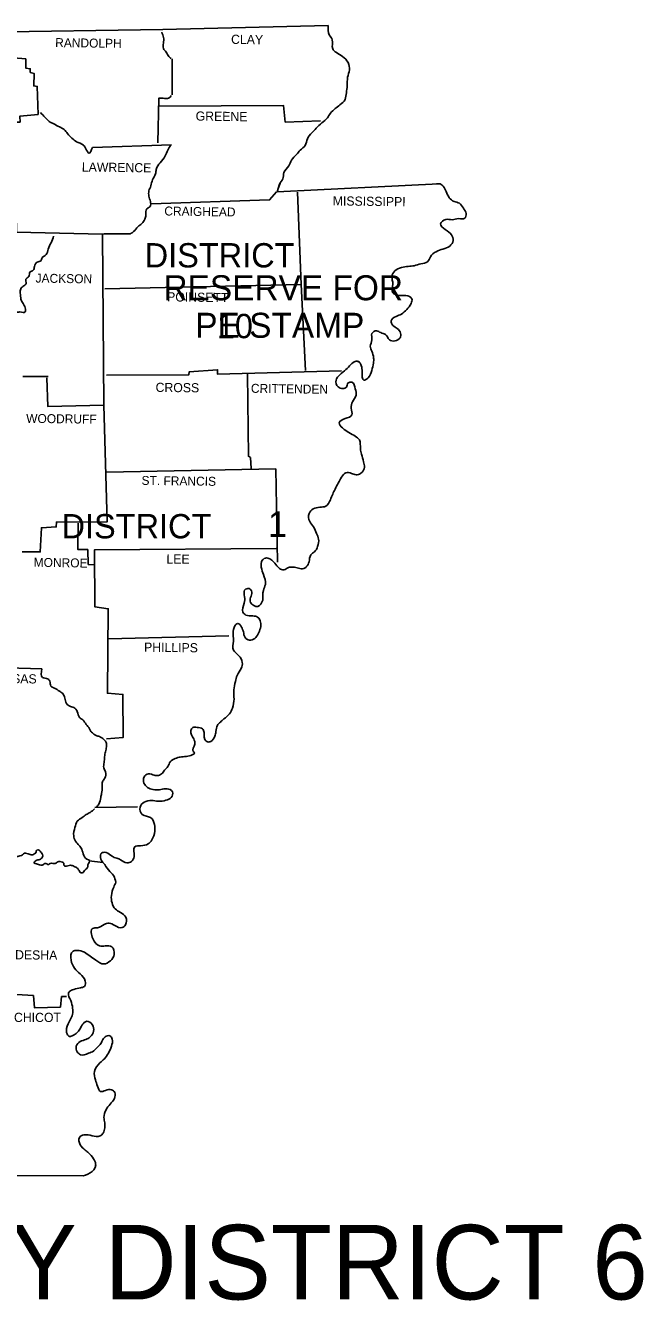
# Model space of a CAD drawing. Extents: x 1096785 to 1382432, y 216169 to 341661.
# Drawn here: x 1237243 to 1243040, y 280666 to 292630 of the extents above; entities that cross this region are included whole.
import ezdxf

# ---------------------------------------------------------------- set-up
doc = ezdxf.new("R2010")
doc.units = 0
for name, color, linetype in [('1', 7, 'Continuous'), ('21', 7, 'Continuous'), ('3', 7, 'Continuous'), ('36', 7, 'Continuous')]:
    doc.layers.add(name, color=color, linetype=linetype)

msp = doc.modelspace()

# ---------------------------------------------------------------- linework, layer by layer
at = {"layer": '1'}
for p, q in [((1239603, 291068), (1239627, 291142)), ((1239609, 291092), (1239633, 291150)), ((1237219, 289336), (1237457, 289336)), ((1237895, 285292), (1238295, 285298)), ((1237967, 284776), (1237841, 284792))]:
    msp.add_line(p, q, dxfattribs=at)
for points in [[(1229111, 292538), (1232345, 292536), (1235183, 292542), (1238531, 292594), (1240083, 292630)], [(1237443, 289324), (1237453, 289054), (1237979, 289068), (1237965, 290672), (1237159, 290690), (1237141, 291722), (1237193, 291724), (1237191, 291780), (1237361, 291796), (1237353, 292058), (1237321, 292064), (1237323, 292180), (1237287, 292190), (1237287, 292224), (1237245, 292230), (1237245, 292316), (1237131, 292328), (1237125, 292424), (1237103, 292438), (1237099, 292470), (1237053, 292480), (1237055, 292504), (1237015, 292510), (1237021, 292558)], [(1238619, 292318), (1238619, 291980)], [(1238483, 291530), (1238493, 291948), (1238493, 291874), (1239663, 291880), (1239679, 291724), (1240009, 291736)], [(1237871, 291486), (1238613, 291512)], [(1239603, 291068), (1241121, 291146)], [(1238423, 290958), (1239533, 290994), (1239599, 291070)], [(1239795, 291066), (1239829, 290200), (1239869, 289394)], [(1238227, 290676), (1237983, 290676), (1237965, 290672)], [(1239829, 290200), (1237987, 290158)], [(1238003, 289348), (1238775, 289352), (1238777, 289380), (1239045, 289400), (1239045, 289358), (1240209, 289390)], [(1239325, 289358), (1239335, 288588), (1239353, 288576), (1239359, 288472)], [(1237979, 289068), (1238009, 287972), (1237533, 287970), (1237531, 287926), (1237393, 287918), (1237381, 287690), (1237213, 287690)], [(1238003, 288438), (1239591, 288470)], [(1239591, 288470), (1239607, 287594)], [(1237737, 287960), (1237735, 287712), (1237827, 287712), (1237831, 287574), (1237889, 287568)], [(1238003, 285938), (1238159, 285948), (1238157, 286354), (1238011, 286364), (1238019, 287158), (1237893, 287176), (1237889, 287710), (1239595, 287722)], [(1238023, 286876), (1239151, 286904)], [(1237397, 286594), (1236641, 286614), (1236637, 286368), (1235107, 286362)], [(1237785, 281836), (1230455, 281848), (1230451, 283466)], [(1237049, 283544), (1237317, 283528), (1237329, 283412), (1237571, 283420), (1237581, 283518), (1237627, 283518)]]:
    msp.add_lwpolyline(points, dxfattribs=at)
for points in [[(1238521, 292568), (1238539, 292518), (1238537, 292464), (1238537, 292414), (1238563, 292380), (1238589, 292338), (1238609, 292320)], [(1240083, 292630), (1240093, 292542), (1240121, 292496), (1240125, 292412), (1240159, 292376), (1240217, 292340), (1240269, 292282), (1240281, 292214), (1240265, 292144), (1240261, 292066), (1240253, 291998), (1240241, 291936), (1240193, 291886), (1240147, 291850), (1240105, 291808), (1240075, 291764), (1240023, 291716), (1239971, 291666), (1239929, 291622), (1239887, 291566), (1239867, 291504), (1239821, 291460), (1239785, 291420), (1239737, 291366), (1239713, 291312), (1239667, 291250), (1239657, 291190), (1239627, 291142), (1239625, 291134)], [(1240083, 292630), (1240093, 292542), (1240121, 292496), (1240125, 292412), (1240159, 292376), (1240217, 292340), (1240269, 292282), (1240281, 292214), (1240265, 292144), (1240261, 292066), (1240253, 291998), (1240241, 291936), (1240193, 291886), (1240147, 291850), (1240105, 291808), (1240075, 291764), (1240023, 291716), (1239971, 291666), (1239929, 291622), (1239887, 291566), (1239867, 291504), (1239821, 291460), (1239785, 291420), (1239737, 291366), (1239713, 291312), (1239667, 291250), (1239657, 291190), (1239627, 291142), (1239625, 291134)], [(1238611, 291974), (1238585, 291948), (1238535, 291948), (1238493, 291948)], [(1237383, 291814), (1237427, 291768), (1237465, 291730), (1237509, 291708), (1237561, 291678), (1237607, 291654), (1237637, 291616), (1237679, 291574), (1237721, 291540), (1237787, 291508), (1237809, 291474), (1237839, 291432), (1237871, 291486)], [(1238607, 291510), (1238577, 291462), (1238553, 291406), (1238505, 291342), (1238469, 291280), (1238463, 291238), (1238435, 291182), (1238419, 291126), (1238401, 291078), (1238401, 291028), (1238415, 290978), (1238411, 290932), (1238381, 290910), (1238373, 290852), (1238361, 290812), (1238335, 290772), (1238297, 290742), (1238257, 290696), (1238227, 290676)], [(1241099, 291144), (1241121, 291146), (1241189, 291074), (1241219, 291014), (1241263, 290980), (1241313, 290962), (1241351, 290916), (1241377, 290866), (1241363, 290822), (1241307, 290818), (1241245, 290808), (1241185, 290810), (1241137, 290770), (1241181, 290716), (1241239, 290666), (1241255, 290612), (1241223, 290560), (1241159, 290532), (1241097, 290508), (1241041, 290460), (1241015, 290414), (1240953, 290394), (1240889, 290376), (1240833, 290370), (1240769, 290358), (1240707, 290328), (1240681, 290276), (1240689, 290202), (1240687, 290124), (1240753, 290098), (1240811, 290096), (1240867, 290066), (1240861, 290022), (1240819, 289966), (1240769, 289922), (1240719, 289900), (1240673, 289858), (1240689, 289816), (1240731, 289788), (1240761, 289742), (1240757, 289700), (1240709, 289670), (1240657, 289682), (1240619, 289732), (1240575, 289748), (1240537, 289766), (1240493, 289740), (1240493, 289682), (1240477, 289620), (1240491, 289574), (1240509, 289510), (1240507, 289462), (1240491, 289394), (1240457, 289324), (1240417, 289302), (1240401, 289378), (1240393, 289440), (1240369, 289476), (1240337, 289478), (1240295, 289448), (1240249, 289402), (1240191, 289352), (1240157, 289302), (1240175, 289240), (1240219, 289224), (1240253, 289236), (1240271, 289276), (1240305, 289282), (1240337, 289220)], [(1241099, 291144), (1241121, 291146), (1241189, 291074), (1241219, 291014), (1241263, 290980), (1241313, 290962), (1241351, 290916), (1241377, 290866), (1241363, 290822), (1241307, 290818), (1241245, 290808), (1241185, 290810), (1241137, 290770), (1241181, 290716), (1241239, 290666), (1241255, 290612), (1241223, 290560), (1241159, 290532), (1241097, 290508), (1241041, 290460), (1241015, 290414), (1240953, 290394), (1240889, 290376), (1240833, 290370), (1240769, 290358), (1240707, 290328), (1240681, 290276), (1240689, 290202), (1240687, 290124), (1240753, 290098), (1240811, 290096), (1240867, 290066), (1240861, 290022), (1240819, 289966), (1240769, 289922), (1240719, 289900), (1240673, 289858), (1240689, 289816), (1240731, 289788), (1240761, 289742), (1240757, 289700), (1240709, 289670), (1240657, 289682), (1240619, 289732), (1240575, 289748), (1240537, 289766), (1240493, 289740), (1240493, 289682), (1240477, 289620), (1240491, 289574), (1240509, 289510), (1240507, 289462), (1240491, 289394), (1240457, 289324), (1240417, 289302), (1240401, 289378), (1240393, 289440), (1240369, 289476), (1240337, 289478), (1240295, 289448), (1240249, 289402), (1240191, 289352), (1240157, 289302), (1240175, 289240), (1240219, 289224), (1240253, 289236), (1240271, 289276), (1240305, 289282), (1240337, 289220)], [(1237507, 290654), (1237483, 290592), (1237455, 290532), (1237437, 290480), (1237399, 290450), (1237387, 290422), (1237353, 290410), (1237327, 290370), (1237315, 290334), (1237287, 290318), (1237273, 290274), (1237247, 290250), (1237249, 290210), (1237219, 290182), (1237195, 290150), (1237195, 290106), (1237205, 290048), (1237225, 290014), (1237243, 289970), (1237241, 289942), (1237191, 289942), (1237149, 289934)], [(1240337, 289220), (1240345, 289162), (1240311, 289100), (1240299, 289038), (1240305, 288976), (1240241, 288942), (1240185, 288902), (1240217, 288854), (1240277, 288810), (1240337, 288776), (1240375, 288742), (1240385, 288660), (1240395, 288608), (1240415, 288536), (1240423, 288486), (1240387, 288426), (1240345, 288414), (1240301, 288428), (1240249, 288432), (1240207, 288392), (1240177, 288336), (1240147, 288280), (1240125, 288232), (1240103, 288180), (1240059, 288120), (1240005, 288110), (1239941, 288094), (1239903, 288050), (1239909, 287976), (1239945, 287926), (1239973, 287864), (1239993, 287810), (1239983, 287742), (1239955, 287692), (1239919, 287662), (1239903, 287598), (1239877, 287550), (1239853, 287534), (1239805, 287538), (1239753, 287548), (1239709, 287544), (1239667, 287522), (1239625, 287536), (1239581, 287584), (1239545, 287620), (1239505, 287634), (1239463, 287612), (1239455, 287546), (1239475, 287478), (1239493, 287386), (1239475, 287330), (1239469, 287238)], [(1240337, 289220), (1240345, 289162), (1240311, 289100), (1240299, 289038), (1240305, 288976), (1240241, 288942), (1240185, 288902), (1240217, 288854), (1240277, 288810), (1240337, 288776), (1240375, 288742), (1240385, 288660), (1240395, 288608), (1240415, 288536), (1240423, 288486), (1240387, 288426), (1240345, 288414), (1240301, 288428), (1240249, 288432), (1240207, 288392), (1240177, 288336), (1240147, 288280), (1240125, 288232), (1240103, 288180), (1240059, 288120), (1240005, 288110), (1239941, 288094), (1239903, 288050), (1239909, 287976), (1239945, 287926), (1239973, 287864), (1239993, 287810), (1239983, 287742), (1239955, 287692), (1239919, 287662), (1239903, 287598), (1239877, 287550), (1239853, 287534), (1239805, 287538), (1239753, 287548), (1239709, 287544), (1239667, 287522), (1239625, 287536), (1239581, 287584), (1239545, 287620), (1239505, 287634), (1239463, 287612), (1239455, 287546), (1239475, 287478), (1239493, 287386), (1239475, 287330), (1239469, 287238)], [(1239469, 287238), (1239423, 287180), (1239355, 287216), (1239355, 287264), (1239365, 287314), (1239341, 287346), (1239299, 287332), (1239299, 287270), (1239295, 287210), (1239283, 287124), (1239311, 287098), (1239375, 287090), (1239421, 287078), (1239449, 287032), (1239447, 286976), (1239425, 286922), (1239393, 286878), (1239343, 286862), (1239303, 286888), (1239287, 286940), (1239269, 286986), (1239235, 287020), (1239199, 286982), (1239191, 286912), (1239193, 286852), (1239193, 286770), (1239245, 286716), (1239277, 286654), (1239267, 286598), (1239229, 286532), (1239213, 286474), (1239197, 286396), (1239199, 286310), (1239185, 286226), (1239157, 286170), (1239105, 286124), (1239071, 286094), (1239043, 286064), (1239029, 286004), (1239019, 285962), (1238981, 285912), (1238951, 285908), (1238927, 285928), (1238919, 285962), (1238919, 285996), (1238903, 286030), (1238853, 286044), (1238813, 286042), (1238795, 286014), (1238821, 285936), (1238831, 285886), (1238817, 285818), (1238825, 285810), (1238753, 285772), (1238695, 285766), (1238647, 285752), (1238601, 285722), (1238579, 285678), (1238547, 285642), (1238519, 285608), (1238481, 285592), (1238439, 285600), (1238383, 285606), (1238351, 285566), (1238361, 285508), (1238399, 285474), (1238455, 285458), (1238513, 285462), (1238569, 285468), (1238621, 285440), (1238611, 285386), (1238561, 285360), (1238487, 285352), (1238427, 285358), (1238355, 285342), (1238319, 285296), (1238339, 285226), (1238417, 285198), (1238453, 285132), (1238455, 285070), (1238429, 284988), (1238393, 284950), (1238323, 284934), (1238269, 284924), (1238261, 284832), (1238237, 284786), (1238195, 284772), (1238135, 284802), (1238099, 284816), (1238055, 284836), (1237999, 284870), (1237957, 284864), (1237969, 284776), (1237973, 284772), (1238021, 284706), (1238069, 284654), (1238091, 284592)], [(1239469, 287238), (1239423, 287180), (1239355, 287216), (1239355, 287264), (1239365, 287314), (1239341, 287346), (1239299, 287332), (1239299, 287270), (1239295, 287210), (1239283, 287124), (1239311, 287098), (1239375, 287090), (1239421, 287078), (1239449, 287032), (1239447, 286976), (1239425, 286922), (1239393, 286878), (1239343, 286862), (1239303, 286888), (1239287, 286940), (1239269, 286986), (1239235, 287020), (1239199, 286982), (1239191, 286912), (1239193, 286852), (1239193, 286770), (1239245, 286716), (1239277, 286654), (1239267, 286598), (1239229, 286532), (1239213, 286474), (1239197, 286396), (1239199, 286310), (1239185, 286226), (1239157, 286170), (1239105, 286124), (1239071, 286094), (1239043, 286064), (1239029, 286004), (1239019, 285962), (1238981, 285912), (1238951, 285908), (1238927, 285928), (1238919, 285962), (1238919, 285996), (1238903, 286030), (1238853, 286044), (1238813, 286042), (1238795, 286014), (1238821, 285936), (1238831, 285886), (1238817, 285818), (1238825, 285810), (1238753, 285772), (1238695, 285766), (1238647, 285752), (1238601, 285722), (1238579, 285678), (1238547, 285642), (1238519, 285608), (1238481, 285592), (1238439, 285600), (1238383, 285606), (1238351, 285566), (1238361, 285508), (1238399, 285474), (1238455, 285458), (1238513, 285462), (1238569, 285468), (1238621, 285440), (1238611, 285386), (1238561, 285360), (1238487, 285352), (1238427, 285358), (1238355, 285342), (1238319, 285296), (1238339, 285226), (1238417, 285198), (1238453, 285132), (1238455, 285070), (1238429, 284988), (1238393, 284950), (1238323, 284934), (1238269, 284924), (1238261, 284832), (1238237, 284786), (1238195, 284772), (1238135, 284802), (1238099, 284816), (1238055, 284836), (1237999, 284870), (1237957, 284864), (1237969, 284776), (1237973, 284772), (1238021, 284706), (1238069, 284654), (1238091, 284592)], [(1237905, 285292), (1237931, 285324), (1237949, 285386), (1237957, 285424), (1237963, 285490), (1237965, 285534), (1237985, 285566), (1237995, 285626), (1237977, 285666), (1237981, 285714), (1237985, 285768), (1237993, 285816), (1238003, 285862), (1238003, 285892), (1237977, 285932), (1237937, 285958), (1237905, 285968), (1237885, 285982), (1237857, 286006), (1237829, 286054), (1237813, 286072), (1237781, 286114), (1237749, 286138), (1237729, 286192), (1237697, 286230), (1237653, 286246), (1237621, 286280), (1237609, 286332), (1237589, 286364), (1237561, 286384), (1237515, 286412), (1237481, 286432), (1237471, 286478), (1237451, 286500), (1237403, 286512), (1237397, 286594)], [(1236637, 285560), (1236667, 285540), (1236709, 285542), (1236737, 285554), (1236759, 285552), (1236789, 285534), (1236809, 285510), (1236823, 285492), (1236833, 285464), (1236833, 285438), (1236843, 285402), (1236855, 285388), (1236871, 285362), (1236881, 285338), (1236887, 285322), (1236909, 285296), (1236929, 285298), (1236947, 285296), (1236971, 285282), (1237007, 285254), (1237013, 285246), (1237037, 285194), (1237041, 285162), (1237045, 285120), (1237053, 285080), (1237069, 285036), (1237077, 285006), (1237095, 284964), (1237107, 284936), (1237123, 284900), (1237147, 284860), (1237157, 284836), (1237191, 284838), (1237215, 284848), (1237233, 284864), (1237255, 284862), (1237279, 284854), (1237311, 284848), (1237331, 284860), (1237341, 284868), (1237343, 284886), (1237361, 284896), (1237381, 284882), (1237403, 284850), (1237403, 284830), (1237395, 284818), (1237369, 284802), (1237333, 284790), (1237323, 284776), (1237357, 284760), (1237411, 284756), (1237425, 284768), (1237461, 284758), (1237475, 284768), (1237523, 284766), (1237545, 284782), (1237589, 284780), (1237603, 284770), (1237603, 284752), (1237639, 284744), (1237665, 284750), (1237699, 284740), (1237729, 284724), (1237745, 284702), (1237765, 284678), (1237783, 284684), (1237797, 284702), (1237827, 284734), (1237827, 284754), (1237835, 284768), (1237845, 284788)], [(1237847, 284794), (1237833, 284800), (1237789, 284842), (1237771, 284902), (1237747, 284936), (1237711, 284978), (1237695, 285026), (1237707, 285106), (1237729, 285164), (1237775, 285198), (1237813, 285226), (1237849, 285246), (1237891, 285280)], [(1238091, 284592), (1238071, 284546), (1238049, 284466), (1238055, 284398), (1238085, 284340), (1238133, 284308), (1238185, 284262), (1238181, 284192), (1238151, 284166), (1238081, 284184), (1238027, 284208), (1237981, 284194), (1237919, 284164), (1237873, 284158), (1237875, 284062), (1237937, 283994), (1237991, 283994), (1238053, 283986), (1238075, 283914), (1238039, 283854), (1237979, 283824), (1237903, 283860), (1237849, 283898), (1237795, 283934), (1237727, 283952), (1237689, 283944), (1237671, 283860), (1237703, 283784), (1237755, 283732), (1237803, 283664), (1237795, 283614), (1237759, 283600), (1237695, 283586), (1237657, 283566), (1237647, 283550), (1237667, 283482), (1237685, 283408), (1237685, 283352), (1237663, 283300), (1237629, 283220), (1237633, 283168), (1237657, 283144), (1237687, 283152), (1237727, 283180), (1237753, 283212), (1237775, 283252), (1237817, 283286), (1237869, 283256), (1237881, 283194), (1237851, 283140), (1237809, 283116), (1237757, 283096), (1237719, 283052), (1237729, 283000), (1237759, 282972), (1237833, 282986), (1237883, 283008), (1237911, 283036), (1237945, 283070), (1237963, 283104), (1237989, 283140), (1238035, 283150), (1238057, 283120), (1238049, 283052), (1238021, 282988), (1237983, 282934), (1237941, 282896), (1237889, 282814), (1237899, 282738), (1237919, 282676), (1237947, 282628), (1237995, 282638), (1238049, 282644), (1238081, 282618), (1238077, 282562), (1238037, 282508), (1237999, 282456), (1237979, 282384), (1237987, 282334), (1237987, 282288), (1237971, 282238), (1237943, 282210), (1237869, 282212), (1237791, 282220), (1237749, 282196), (1237757, 282128), (1237803, 282078), (1237835, 282052), (1237881, 281996), (1237901, 281950), (1237895, 281910), (1237867, 281876), (1237785, 281836)], [(1238091, 284592), (1238071, 284546), (1238049, 284466), (1238055, 284398), (1238085, 284340), (1238133, 284308), (1238185, 284262), (1238181, 284192), (1238151, 284166), (1238081, 284184), (1238027, 284208), (1237981, 284194), (1237919, 284164), (1237873, 284158), (1237875, 284062), (1237937, 283994), (1237991, 283994), (1238053, 283986), (1238075, 283914), (1238039, 283854), (1237979, 283824), (1237903, 283860), (1237849, 283898), (1237795, 283934), (1237727, 283952), (1237689, 283944), (1237671, 283860), (1237703, 283784), (1237755, 283732), (1237803, 283664), (1237795, 283614), (1237759, 283600), (1237695, 283586), (1237657, 283566), (1237647, 283550), (1237667, 283482), (1237685, 283408), (1237685, 283352), (1237663, 283300), (1237629, 283220), (1237633, 283168), (1237657, 283144), (1237687, 283152), (1237727, 283180), (1237753, 283212), (1237775, 283252), (1237817, 283286), (1237869, 283256), (1237881, 283194), (1237851, 283140), (1237809, 283116), (1237757, 283096), (1237719, 283052), (1237729, 283000), (1237759, 282972), (1237833, 282986), (1237883, 283008), (1237911, 283036), (1237945, 283070), (1237963, 283104), (1237989, 283140), (1238035, 283150), (1238057, 283120), (1238049, 283052), (1238021, 282988), (1237983, 282934), (1237941, 282896), (1237889, 282814), (1237899, 282738), (1237919, 282676), (1237947, 282628), (1237995, 282638), (1238049, 282644), (1238081, 282618), (1238077, 282562), (1238037, 282508), (1237999, 282456), (1237979, 282384), (1237987, 282334), (1237987, 282288), (1237971, 282238), (1237943, 282210), (1237869, 282212), (1237791, 282220), (1237749, 282196), (1237757, 282128), (1237803, 282078), (1237835, 282052), (1237881, 281996), (1237901, 281950), (1237895, 281910), (1237867, 281876), (1237785, 281836)]]:
    msp.add_spline(points, degree=3, dxfattribs=at)

# ---------------------------------------------------------------- texts
msp.add_text('1', height=240, dxfattribs=at).set_placement((1239517, 287832))
at = {"layer": '21'}
for s, p in [('DISTRICT', (1238361, 290360)), ('10', (1239037, 289696)), ('DISTRICT', (1237581, 287818))]:
    msp.add_text(s, height=228, dxfattribs=at).set_placement(p)
at = {"layer": '3'}
for s, height, rotation, p in [('CLAY', 86, 359.2258, (1239171, 292458)), ('RANDOLPH', 84, 359.2583, (1237521, 292428)), ('GREENE', 86, 359.2361, (1238839, 291738)), ('LAWRENCE', 86, 359.2678, (1237771, 291260)), ('MISSISSIPPI', 85.99, 359.3097, (1240125, 290942)), ('CRAIGHEAD', 84, 359.1159, (1238545, 290848)), ('JACKSON', 84, 359.1352, (1237337, 290218)), ('POINSETT', 86, 359.1987, (1238571, 290042)), ('CROSS', 86, 359.3839, (1238463, 289192)), ('CRITTENDEN', 84, 359.213, (1239357, 289184)), ('WOODRUFF', 84, 359.2748, (1237249, 288902)), ('ST. FRANCIS', 83.99, 359.2216, (1238331, 288320)), ('MONROE', 84, 359.0331, (1237319, 287552)), ('LEE', 86, 359.4327, (1238565, 287582)), ('PHILLIPS', 86, 359.3179, (1238355, 286754)), ('ARKANSAS', 86, 359.2678, (1236721, 286464)), ('DESHA', 86, 359.3704, (1237145, 283868))]:
    msp.add_text(s, height=height, rotation=rotation, dxfattribs=at).set_placement(p)
for s, height, p in [('CHICOT', 86, (1237135, 283280)), ('ARKANSAS HIGHWAY DISTRICT 6', 700, (1227894, 280676))]:
    msp.add_text(s, height=height, dxfattribs=at).set_placement(p)
at = {"layer": '36'}
for s, height, p in [('RESERVE FOR ', 234.48, (1238537, 290052)), ('PE STAMP', 234.5, (1238836, 289700))]:
    msp.add_text(s, height=height, dxfattribs=at).set_placement(p)

doc.saveas('drawing.dxf')
